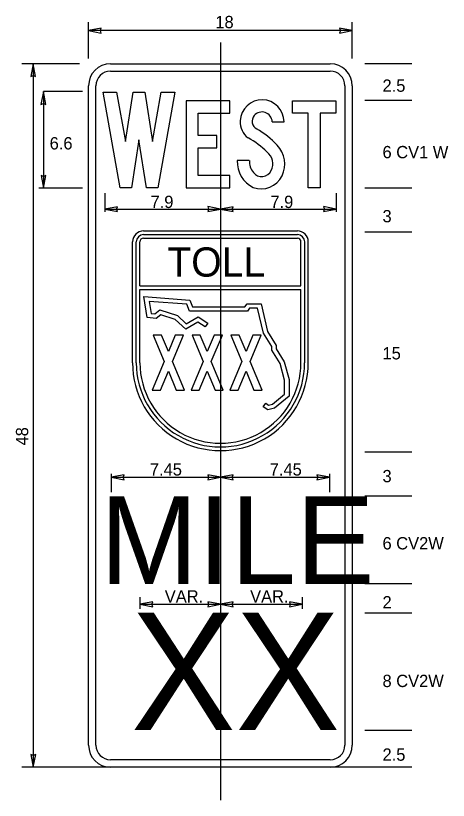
# Model space of a CAD drawing. Extents: x 56108 to 56738, y 11696 to 12112.
# Drawn here: x 56520.2 to 56618.7, y 11931.8 to 12110.3 of the extents above; entities that cross this region are included whole.
import ezdxf

# ---------------------------------------------------------------- set-up
doc = ezdxf.new("R2010")
doc.units = 0
for name, color, linetype in [('CL_dp', 7, 'Continuous'), ('GSDims', 7, 'Continuous'), ('SignDetail', 7, 'Continuous'), ('SignPanel', 7, 'Continuous')]:
    doc.layers.add(name, color=color, linetype=linetype)

msp = doc.modelspace()

# ---------------------------------------------------------------- linework, layer by layer
at = {"layer": 'CL_dp'}
msp.add_line((56566.81, 12104.19), (56566.81, 11931.84), dxfattribs=at)
at = {"layer": 'GSDims'}
for p, q in [((56536.81, 12100.62), (56536.81, 12108.84)), ((56596.81, 12100.62), (56596.81, 12108.84)), ((56539.71, 12107.46), (56536.81, 12106.92)), ((56596.81, 12106.92), (56536.81, 12106.92)), ((56536.81, 12106.92), (56539.71, 12106.36)), ((56539.49, 12106.92), (56539.71, 12107.46)), ((56539.71, 12106.36), (56539.49, 12106.92)), ((56596.81, 12106.92), (56593.91, 12107.48)), ((56593.91, 12107.48), (56594.13, 12106.92)), ((56594.13, 12106.92), (56593.91, 12106.38)), ((56593.91, 12106.38), (56596.81, 12106.92)), ((56534.73, 12099.38), (56521.6, 12099.38)), ((56524.22, 12099.38), (56523.66, 12096.48)), ((56524.22, 12099.38), (56524.22, 11939.38)), ((56524.76, 12096.48), (56524.22, 12099.38)), ((56610.35, 12099.38), (56599.67, 12099.38)), ((56523.66, 12096.48), (56524.22, 12096.7)), ((56524.22, 12096.7), (56524.76, 12096.48)), ((56526.53, 12093.05), (56525.97, 12090.15)), ((56526.53, 12093.05), (56526.53, 12071.05)), ((56535.4, 12093.05), (56526.53, 12093.05)), ((56527.07, 12090.15), (56526.53, 12093.05)), ((56610.35, 12091.05), (56599.67, 12091.05)), ((56525.97, 12090.15), (56526.53, 12090.37)), ((56526.53, 12090.37), (56527.07, 12090.15)), ((56526.53, 12073.73), (56525.99, 12073.95)), ((56525.99, 12073.95), (56526.53, 12071.05)), ((56526.53, 12071.05), (56527.09, 12073.95)), ((56527.09, 12073.95), (56526.53, 12073.73)), ((56535.4, 12071.05), (56525.48, 12071.05)), ((56610.35, 12071.05), (56599.67, 12071.05)), ((56540.48, 12069.96), (56540.48, 12065.71)), ((56593.14, 12069.96), (56593.14, 12065.71)), ((56543.38, 12066.87), (56540.48, 12066.33)), ((56540.48, 12066.33), (56566.81, 12066.33)), ((56540.48, 12066.33), (56543.38, 12065.77)), ((56543.16, 12066.33), (56543.38, 12066.87)), ((56543.38, 12065.77), (56543.16, 12066.33)), ((56566.81, 12066.33), (56563.91, 12066.89)), ((56563.91, 12066.89), (56564.13, 12066.33)), ((56564.13, 12066.33), (56563.91, 12065.79)), ((56563.91, 12065.79), (56566.81, 12066.33)), ((56569.71, 12066.87), (56566.81, 12066.33)), ((56566.81, 12066.33), (56593.14, 12066.33)), ((56566.81, 12066.33), (56569.71, 12065.77)), ((56569.49, 12066.33), (56569.71, 12066.87)), ((56569.71, 12065.77), (56569.49, 12066.33)), ((56593.14, 12066.33), (56590.24, 12066.89)), ((56590.24, 12066.89), (56590.46, 12066.33)), ((56590.46, 12066.33), (56590.24, 12065.79)), ((56590.24, 12065.79), (56593.14, 12066.33)), ((56610.35, 12061.05), (56599.67, 12061.05)), ((56554.94, 12044.95), (56554.94, 12044.95)), ((56610.35, 12011.05), (56599.67, 12011.05)), ((56541.98, 12006.1), (56541.98, 12001.97)), ((56544.88, 12005.85), (56541.98, 12005.31)), ((56541.98, 12005.31), (56566.81, 12005.31)), ((56541.98, 12005.31), (56544.88, 12004.75)), ((56544.66, 12005.31), (56544.88, 12005.85)), ((56544.88, 12004.75), (56544.66, 12005.31)), ((56566.81, 12005.31), (56563.91, 12005.87)), ((56563.91, 12005.87), (56564.13, 12005.31)), ((56564.13, 12005.31), (56563.91, 12004.77)), ((56563.91, 12004.77), (56566.81, 12005.31)), ((56569.71, 12005.85), (56566.81, 12005.31)), ((56566.81, 12005.31), (56591.64, 12005.31)), ((56566.81, 12005.31), (56569.71, 12004.75)), ((56569.49, 12005.31), (56569.71, 12005.85)), ((56569.71, 12004.75), (56569.49, 12005.31)), ((56591.64, 12005.31), (56588.74, 12005.87)), ((56588.74, 12005.87), (56588.96, 12005.31)), ((56588.96, 12005.31), (56588.74, 12004.77)), ((56588.74, 12004.77), (56591.64, 12005.31)), ((56591.64, 12006.1), (56591.64, 12001.97)), ((56610.35, 12001.05), (56599.67, 12001.05)), ((56610.35, 11981.05), (56599.67, 11981.05)), ((56548.51, 11978.07), (56548.51, 11975.38)), ((56585.39, 11978.07), (56585.39, 11975.38)), ((56551.41, 11976.96), (56548.51, 11976.42)), ((56548.51, 11976.42), (56566.81, 11976.42)), ((56548.51, 11976.42), (56551.41, 11975.86)), ((56551.19, 11976.42), (56551.41, 11976.96)), ((56551.41, 11975.86), (56551.19, 11976.42)), ((56566.81, 11976.42), (56563.91, 11976.98)), ((56563.91, 11976.98), (56564.13, 11976.42)), ((56564.13, 11976.42), (56563.91, 11975.88)), ((56563.91, 11975.88), (56566.81, 11976.42)), ((56569.71, 11976.96), (56566.81, 11976.42)), ((56566.81, 11976.42), (56585.39, 11976.42)), ((56566.81, 11976.42), (56569.71, 11975.86)), ((56569.49, 11976.42), (56569.71, 11976.96)), ((56569.71, 11975.86), (56569.49, 11976.42)), ((56585.39, 11976.42), (56582.49, 11976.98)), ((56582.49, 11976.98), (56582.71, 11976.42)), ((56582.71, 11976.42), (56582.49, 11975.88)), ((56582.49, 11975.88), (56585.39, 11976.42)), ((56610.35, 11974.38), (56599.67, 11974.38)), ((56610.35, 11947.71), (56599.67, 11947.71)), ((56524.22, 11942.06), (56523.68, 11942.28)), ((56523.68, 11942.28), (56524.22, 11939.38)), ((56524.22, 11939.38), (56524.78, 11942.28)), ((56524.78, 11942.28), (56524.22, 11942.06)), ((56534.73, 11939.38), (56521.6, 11939.38)), ((56610.35, 11939.38), (56527.07, 11939.38))]:
    msp.add_line(p, q, dxfattribs=at)
at = {"layer": 'SignDetail'}
for p, q in [((56549.31, 12061.38), (56584.32, 12061.38)), ((56549.31, 12060.54), (56584.32, 12060.54)), ((56546.81, 12031.37), (56546.81, 12058.88)), ((56547.65, 12031.37), (56547.65, 12058.88)), ((56548.47, 12048.89), (56548.47, 12058.88)), ((56549.31, 12059.7), (56584.32, 12059.7)), ((56585.14, 12048.89), (56585.14, 12058.88)), ((56585.98, 12031.37), (56585.98, 12058.88)), ((56586.81, 12031.37), (56586.81, 12058.88)), ((56548.47, 12048.89), (56585.14, 12048.89)), ((56548.47, 12031.37), (56548.47, 12048.05)), ((56548.47, 12048.05), (56585.14, 12048.05)), ((56585.14, 12031.37), (56585.14, 12048.05))]:
    msp.add_line(p, q, dxfattribs=at)
for centre, major_axis, start_param, end_param in [((56549.32, 12058.87), (0, 2.5), 0, 1.570796), ((56549.32, 12058.87), (0, 1.67), 0, 1.570796), ((56584.31, 12058.87), (0, 2.5), 4.712389, 6.283185), ((56584.31, 12058.87), (0, 1.67), 4.712389, 6.283185), ((56549.32, 12058.87), (0, 0.833), 0, 1.570796), ((56584.31, 12058.87), (0, 0.833), 4.712389, 6.283185), ((56566.81, 12031.38), (0, -20), 4.712389, 7.853982), ((56566.81, 12031.38), (0, -19.16), 4.712389, 7.853982), ((56566.81, 12031.38), (0, -18.33), 4.712389, 7.853982)]:
    msp.add_ellipse(centre, major_axis=major_axis, ratio=0.9997, start_param=start_param, end_param=end_param, dxfattribs=at)
at = {"layer": 'SignPanel'}
for p, q in [((56578.62, 12086.19), (56581.31, 12086.19)), ((56578.62, 12086.19), (56581.31, 12086.19)), ((56578.62, 12086.19), (56581.31, 12086.19)), ((56573.38, 12077.39), (56570.65, 12077.39)), ((56573.38, 12077.39), (56570.65, 12077.39)), ((56573.38, 12077.39), (56570.65, 12077.39)), ((56550.16, 12041.66), (56549.42, 12046.44)), ((56549.42, 12046.44), (56559.85, 12045.63)), ((56559.14, 12044.68), (56550.61, 12045.33)), ((56550.61, 12045.33), (56551.04, 12042.57)), ((56559.75, 12043.12), (56559.14, 12044.68)), ((56559.85, 12045.63), (56560.44, 12044.13)), ((56560.44, 12044.13), (56572.4, 12044.13)), ((56572.4, 12044.13), (56572.86, 12044.8)), ((56572.86, 12044.8), (56576.08, 12044.8)), ((56576.08, 12044.8), (56577.53, 12038.52)), ((56551.04, 12042.57), (56551.86, 12042.47)), ((56551.86, 12042.47), (56553.05, 12043.4)), ((56553.25, 12042.28), (56552.16, 12041.42)), ((56553.05, 12043.4), (56557.08, 12042.09)), ((56556.55, 12041.2), (56553.25, 12042.28)), ((56572.94, 12043.12), (56559.75, 12043.12)), ((56573.39, 12043.79), (56572.94, 12043.12)), ((56575.28, 12043.79), (56573.39, 12043.79)), ((56576.59, 12038.13), (56575.28, 12043.79)), ((56552.16, 12041.42), (56550.16, 12041.66)), ((56558.92, 12039.01), (56556.55, 12041.2)), ((56557.08, 12042.09), (56559.05, 12040.26)), ((56561.69, 12040.64), (56558.92, 12039.01)), ((56559.05, 12040.26), (56561.73, 12041.83)), ((56563.35, 12039.53), (56561.69, 12040.64)), ((56561.73, 12041.83), (56563.91, 12040.36)), ((56563.91, 12040.36), (56563.35, 12039.53)), ((56578.51, 12035.05), (56576.59, 12038.13)), ((56577.53, 12038.52), (56579.52, 12035.33)), ((56579.52, 12035.33), (56579.52, 12034.53)), ((56578.51, 12034.25), (56578.51, 12035.05)), ((56580.38, 12031.17), (56578.51, 12034.25)), ((56579.52, 12034.53), (56581.31, 12031.57)), ((56581.31, 12031.57), (56582.42, 12027.53)), ((56581.41, 12027.39), (56580.38, 12031.17)), ((56581.41, 12024.23), (56581.41, 12027.39)), ((56582.42, 12027.53), (56582.42, 12023.75)), ((56578.66, 12021.97), (56581.41, 12024.23)), ((56582.42, 12023.75), (56579.12, 12021.05)), ((56576.56, 12021.36), (56577.14, 12022.19)), ((56577.56, 12020.67), (56576.56, 12021.36)), ((56577.14, 12022.19), (56577.76, 12021.76)), ((56579.12, 12021.05), (56577.56, 12020.67)), ((56577.76, 12021.76), (56578.66, 12021.97))]:
    msp.add_line(p, q, dxfattribs=at)
for points in [[(56541.81, 12099.38), (56591.81, 12099.38)], [(56541.81, 12097.71), (56591.81, 12097.71)], [(56536.81, 11944.38), (56536.81, 12094.38)], [(56538.48, 11944.38), (56538.48, 12094.38)], [(56595.14, 12094.38), (56595.14, 11944.38)], [(56596.81, 12094.38), (56596.81, 11944.38)], [(56591.81, 11941.05), (56541.81, 11941.05)], [(56591.81, 11939.38), (56541.81, 11939.38)]]:
    msp.add_lwpolyline(points, dxfattribs=at)
for points in [[(56545.18, 12081.68), (56546.95, 12092.92), (56549.59, 12092.92), (56551.36, 12081.68), (56553.36, 12092.92), (56556.4, 12092.92), (56552.55, 12071.2), (56549.98, 12071.2), (56548.27, 12082.06), (56546.56, 12071.2), (56543.99, 12071.2), (56540.14, 12092.92), (56543.19, 12092.92)], [(56545.18, 12081.68), (56546.95, 12092.92), (56549.59, 12092.92), (56551.36, 12081.68), (56553.36, 12092.92), (56556.4, 12092.92), (56552.55, 12071.2), (56549.98, 12071.2), (56548.27, 12082.06), (56546.56, 12071.2), (56543.99, 12071.2), (56540.14, 12092.92), (56543.19, 12092.92)], [(56545.18, 12081.68), (56546.95, 12092.92), (56549.59, 12092.92), (56551.36, 12081.68), (56553.36, 12092.92), (56556.4, 12092.92), (56552.55, 12071.2), (56549.98, 12071.2), (56548.27, 12082.06), (56546.56, 12071.2), (56543.99, 12071.2), (56540.14, 12092.92), (56543.19, 12092.92)], [(56561.76, 12073.96), (56561.76, 12080.28), (56566.02, 12080.28), (56566.02, 12083.05), (56561.76, 12083.05), (56561.76, 12088.18), (56568.95, 12088.18), (56568.95, 12090.94), (56559.03, 12090.94), (56559.03, 12071.2), (56568.95, 12071.2), (56568.95, 12073.96)], [(56561.76, 12073.96), (56561.76, 12080.28), (56566.02, 12080.28), (56566.02, 12083.05), (56561.76, 12083.05), (56561.76, 12088.18), (56568.95, 12088.18), (56568.95, 12090.94), (56559.03, 12090.94), (56559.03, 12071.2), (56568.95, 12071.2), (56568.95, 12073.96)], [(56561.76, 12073.96), (56561.76, 12080.28), (56566.02, 12080.28), (56566.02, 12083.05), (56561.76, 12083.05), (56561.76, 12088.18), (56568.95, 12088.18), (56568.95, 12090.94), (56559.03, 12090.94), (56559.03, 12071.2), (56568.95, 12071.2), (56568.95, 12073.96)], [(56586.77, 12088.18), (56583.18, 12088.18), (56583.18, 12090.94), (56593.1, 12090.94), (56593.1, 12088.18), (56589.5, 12088.18), (56589.5, 12071.2), (56586.77, 12071.2)], [(56586.77, 12088.18), (56583.18, 12088.18), (56583.18, 12090.94), (56593.1, 12090.94), (56593.1, 12088.18), (56589.5, 12088.18), (56589.5, 12071.2), (56586.77, 12071.2)], [(56586.77, 12088.18), (56583.18, 12088.18), (56583.18, 12090.94), (56593.1, 12090.94), (56593.1, 12088.18), (56589.5, 12088.18), (56589.5, 12071.2), (56586.77, 12071.2)], [(56553.18, 12025.15), (56554.97, 12029.43), (56556.76, 12025.15), (56558.63, 12025.15), (56555.9, 12031.67), (56558.41, 12037.65), (56556.54, 12037.65), (56554.97, 12033.9), (56553.4, 12037.65), (56551.52, 12037.65), (56554.03, 12031.67), (56551.3, 12025.15)], [(56562.01, 12025.15), (56563.8, 12029.43), (56565.59, 12025.15), (56567.47, 12025.15), (56564.74, 12031.67), (56567.25, 12037.65), (56565.37, 12037.65), (56563.8, 12033.9), (56562.23, 12037.65), (56560.36, 12037.65), (56562.87, 12031.67), (56560.14, 12025.15)], [(56570.85, 12025.15), (56572.64, 12029.43), (56574.43, 12025.15), (56576.3, 12025.15), (56573.58, 12031.67), (56576.08, 12037.65), (56574.21, 12037.65), (56572.64, 12033.9), (56571.07, 12037.65), (56569.2, 12037.65), (56571.7, 12031.67), (56568.98, 12025.15)]]:
    msp.add_lwpolyline(points, close=True, dxfattribs=at)
for centre, radius, start, end in [((56541.81, 12094.38), 5, 90, 180), ((56591.81, 12094.38), 5, 0, 90), ((56541.81, 12094.38), 3.33, 90, 180), ((56591.81, 12094.38), 3.33, 0, 90), ((56541.81, 11944.38), 5, 180, 270), ((56541.81, 11944.38), 3.33, 180, 270), ((56591.81, 11944.38), 5, 270, 360), ((56591.81, 11944.38), 3.33, 270, 360)]:
    msp.add_arc(centre, radius, start, end, dxfattribs=at)
for centre, major_axis, start_param, end_param in [((56576.29, 12086.07), (0, 5.12), 4.736267, 7.790596), ((56576.29, 12086.07), (0, 5.12), 4.736267, 7.790596), ((56576.29, 12086.07), (0, 5.12), 4.736267, 7.790596), ((56575.97, 12086.31), (0, 1.99), 0.87378, 2.656959), ((56575.97, 12086.31), (0, 1.99), 0.87378, 2.656959), ((56575.97, 12086.31), (0, 1.99), 0.87378, 2.656959), ((56576.26, 12086.01), (0, 2.41), 4.786904, 7.140738), ((56576.26, 12086.01), (0, 2.41), 4.786904, 7.140738), ((56576.26, 12086.01), (0, 2.41), 4.786904, 7.140738), ((56575.78, 12086.23), (0, 4.6), 1.534831, 2.511766), ((56575.78, 12086.23), (0, 4.6), 1.534831, 2.511766), ((56575.78, 12086.23), (0, 4.6), 1.534831, 2.511766), ((56566.13, 12067.94), (0, 18.94), 5.462886, 5.782242), ((56566.13, 12067.94), (0, 18.94), 5.462886, 5.782242), ((56566.13, 12067.94), (0, 18.94), 5.462886, 5.782242), ((56563.78, 12064.92), (0, 20), 5.515137, 5.786988), ((56563.78, 12064.92), (0, 20), 5.515137, 5.786988), ((56563.78, 12064.92), (0, 20), 5.515137, 5.786988), ((56575.43, 12076.58), (0, 6.12), 4.260987, 5.485755), ((56575.43, 12076.58), (0, 6.12), 4.260987, 5.485755), ((56575.43, 12076.58), (0, 6.12), 4.260987, 5.485755), ((56575.38, 12076.59), (0, 3.42), 4.254409, 5.632398), ((56575.38, 12076.59), (0, 3.42), 4.254409, 5.632398), ((56575.38, 12076.59), (0, 3.42), 4.254409, 5.632398), ((56576.97, 12077.1), (0, 6.45), 1.526364, 2.701682), ((56576.97, 12077.1), (0, 6.45), 1.526364, 2.701682), ((56576.97, 12077.1), (0, 6.45), 1.526364, 2.701682), ((56577.24, 12077.21), (0, 3.93), 1.524757, 2.28214), ((56577.24, 12077.21), (0, 3.93), 1.524757, 2.28214), ((56577.24, 12077.21), (0, 3.93), 1.524757, 2.28214), ((56576.21, 12076.24), (0, 2.51), 2.261787, 4.23006), ((56576.21, 12076.24), (0, 2.51), 2.261787, 4.23006), ((56576.21, 12076.24), (0, 2.51), 2.261787, 4.23006), ((56576.11, 12076.3), (0, 5.37), 2.786047, 4.251692), ((56576.11, 12076.3), (0, 5.37), 2.786047, 4.251692), ((56576.11, 12076.3), (0, 5.37), 2.786047, 4.251692)]:
    msp.add_ellipse(centre, major_axis=major_axis, ratio=0.981197, start_param=start_param, end_param=end_param, dxfattribs=at)

# ---------------------------------------------------------------- texts
at = {"layer": 'GSDims'}
for s, p in [('18', (56565.65, 12107.48)), ('2.5', (56603.69, 12093.01)), ('6.6', (56527.95, 12079.9)), ('6 CV1 W', (56603.69, 12077.89)), ('7.9', (56550.91, 12066.57)), ('7.9', (56578.18, 12066.57)), ('3', (56603.69, 12063.32)), ('15', (56603.69, 12032.13)), ('7.45', (56550.76, 12005.71)), ('7.45', (56578.03, 12005.71)), ('3', (56603.69, 12004.19)), ('6 CV2W', (56603.69, 11988.91)), ('VAR.', (56554.15, 11976.82)), ('VAR.', (56573.57, 11976.82)), ('2', (56603.69, 11975.49)), ('8 CV2W', (56603.69, 11957.6)), ('2.5', (56603.69, 11940.84))]:
    msp.add_text(s, height=2.8, dxfattribs=at).set_placement(p)
msp.add_text('48', height=2.8, rotation=90, dxfattribs=at).set_placement((56523.07, 12012.55))
at = {"layer": 'SignDetail'}
msp.add_text('TOLL', height=6.659, dxfattribs=at).set_placement((56554.73, 12050.96))
at = {"layer": 'SignPanel'}
for s, height, p in [('MILE', 20, (56539.4, 11981.02)), ('XX', 26.667, (56546.46, 11947.85))]:
    msp.add_text(s, height=height, dxfattribs=at).set_placement(p)

doc.saveas('drawing.dxf')
